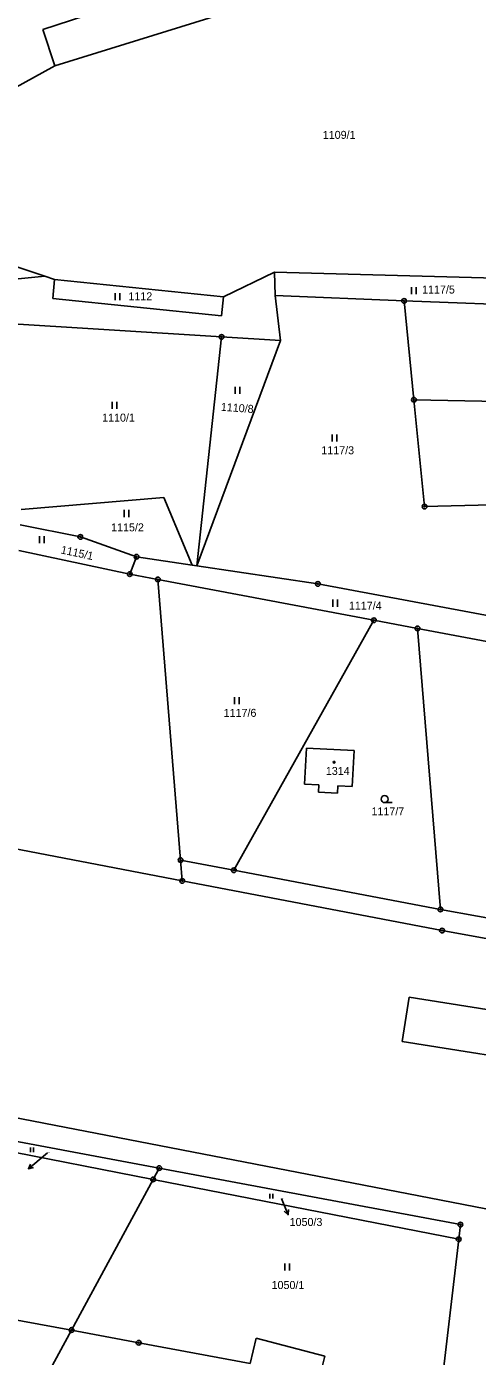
# Model space of a CAD drawing. Extents: x -439246 to -433691, y -1130252 to -1121148.
# Drawn here: x -438252.9 to -438157.2, y -1124120.8 to -1123838.4 of the extents above; entities that cross this region are included whole.
import ezdxf

# ---------------------------------------------------------------- set-up
doc = ezdxf.new("R2010")
doc.units = 0
for name, color, linetype in [('Vrstva 1', 7, 'Continuous'), ('Vrstva 16', 7, 'Continuous'), ('Vrstva 18', 7, 'Continuous'), ('Vrstva 19', 7, 'Continuous'), ('Vrstva 24', 7, 'Continuous'), ('Vrstva 25', 7, 'Continuous'), ('Vrstva 3', 7, 'Continuous'), ('Vrstva 37', 7, 'Continuous'), ('Vrstva 4', 7, 'Continuous')]:
    doc.layers.add(name, color=color, linetype=linetype)

msp = doc.modelspace()

# ---------------------------------------------------------------- linework, layer by layer
at = {"layer": 'Vrstva 1'}
for p, q in [((-438211.48, -1123904.28), (-438259.95, -1123901.23)), ((-438216.73, -1123952.89), (-438211.48, -1123904.28)), ((-438211.48, -1123904.28), (-438199.01, -1123905.06)), ((-438154.2, -1123939.93), (-438168.37, -1123940.3)), ((-438254.26, -1123944.18), (-438241.49, -1123946.76)), ((-438241.49, -1123946.76), (-438229.55, -1123950.97)), ((-438152.43, -1123963.95), (-438191.04, -1123956.73)), ((-438303.51, -1124068.13), (-438226.05, -1124083.23)), ((-438226.05, -1124083.23), (-438243.36, -1124115.21)), ((-438226.05, -1124083.23), (-438161.14, -1124095.94)), ((-438161.14, -1124095.94), (-438165.06, -1124129.7))]:
    msp.add_line(p, q, dxfattribs=at)
for points in [[(-438158.58, -1123809.31), (-438249.45, -1123838.99)], [(-438246.94, -1123846.69), (-438161.58, -1123820.18)], [(-438249.45, -1123838.99), (-438246.94, -1123846.69)], [(-438246.94, -1123846.69), (-438262.62, -1123855.3)], [(-438263.58, -1123886.54), (-438249.05, -1123891.36)], [(-438288.53, -1123895.35), (-438249.05, -1123891.36)], [(-438249.05, -1123891.36), (-438246.95, -1123892.05)], [(-438246.95, -1123892.05), (-438247.36, -1123896.13)], [(-438246.95, -1123892.05), (-438211.07, -1123895.72)], [(-438211.07, -1123895.72), (-438200.28, -1123890.51)], [(-438200.28, -1123890.51), (-438200.11, -1123895.5)], [(-438200.28, -1123890.51), (-438142.74, -1123892.06)], [(-438211.07, -1123895.72), (-438211.49, -1123899.79)], [(-438200.11, -1123895.5), (-438172.73, -1123896.63)], [(-438200.11, -1123895.5), (-438199.01, -1123905.06)], [(-438247.36, -1123896.13), (-438211.49, -1123899.79)], [(-438172.73, -1123896.63), (-438142.74, -1123897.72)], [(-438172.73, -1123896.63), (-438170.63, -1123917.63)], [(-438199.01, -1123905.06), (-438216.73, -1123952.89)], [(-438170.63, -1123917.63), (-438091.35, -1123919.18)], [(-438170.63, -1123917.63), (-438168.37, -1123940.3)], [(-438223.73, -1123938.4), (-438254.07, -1123940.9)], [(-438217.77, -1123952.73), (-438223.73, -1123938.4)], [(-438231, -1123954.66), (-438254.58, -1123949.65)], [(-438229.55, -1123950.97), (-438231, -1123954.66)], [(-438229.55, -1123950.97), (-438217.77, -1123952.73)], [(-438231, -1123954.66), (-438225.03, -1123955.79)], [(-438217.77, -1123952.73), (-438216.73, -1123952.89)], [(-438216.73, -1123952.89), (-438191.04, -1123956.73)], [(-438220.2, -1124015.39), (-438225.03, -1123955.79)], [(-438225.03, -1123955.79), (-438179.13, -1123964.45)], [(-438179.13, -1123964.45), (-438208.88, -1124017.54)], [(-438179.13, -1123964.45), (-438169.88, -1123966.2)], [(-438169.88, -1123966.2), (-438139.3, -1123971.97)], [(-438169.88, -1123966.2), (-438165.03, -1124025.88)], [(-438193.88, -1123999.25), (-438193.49, -1123991.62)], [(-438193.49, -1123991.62), (-438183.35, -1123992.11)], [(-438183.35, -1123992.11), (-438183.74, -1123999.75)], [(-438190.87, -1123999.4), (-438193.88, -1123999.25)], [(-438190.94, -1124000.95), (-438190.87, -1123999.4)], [(-438186.78, -1123999.62), (-438186.86, -1124001.16)], [(-438183.74, -1123999.75), (-438186.78, -1123999.62)], [(-438186.86, -1124001.16), (-438190.94, -1124000.95)], [(-438289.96, -1124006.37), (-438219.84, -1124019.83)], [(-438219.84, -1124019.83), (-438220.2, -1124015.39)], [(-438208.88, -1124017.54), (-438220.2, -1124015.39)], [(-438219.84, -1124019.83), (-438164.68, -1124030.36)], [(-438165.03, -1124025.88), (-438208.88, -1124017.54)], [(-438165.03, -1124025.88), (-438141.4, -1124030.14)], [(-438164.68, -1124030.36), (-438099.78, -1124042.19)], [(-438308.2, -1124065.16), (-438224.74, -1124080.81)], [(-438292.1, -1124062.98), (-438190.79, -1124082.63)], [(-438226.05, -1124083.23), (-438224.74, -1124080.81)], [(-438224.74, -1124080.81), (-438160.78, -1124092.83)], [(-438190.79, -1124082.63), (-438089.34, -1124102.31)], [(-438161.14, -1124095.94), (-438160.78, -1124092.83)], [(-438243.36, -1124115.21), (-438298.17, -1124105.16)], [(-438243.36, -1124115.21), (-438251.93, -1124131.05)], [(-438229.1, -1124117.92), (-438243.36, -1124115.21)], [(-438205.45, -1124122.3), (-438229.1, -1124117.92)], [(-438204.13, -1124116.96), (-438205.45, -1124122.3)], [(-438189.56, -1124120.76), (-438204.13, -1124116.96)], [(-438190.66, -1124124.99), (-438189.56, -1124120.76)]]:
    msp.add_lwpolyline(points, dxfattribs=at)
at = {"layer": 'Vrstva 16'}
for p, q in [((-438250.22, -1124079.06), (-438252.53, -1124080.97)), ((-438198.51, -1124087.96), (-438197.34, -1124090.72))]:
    msp.add_line(p, q, dxfattribs=at)
for points in [[(-438248.44, -1124077.58), (-438250.22, -1124079.06)], [(-438251.44, -1124080.72), (-438252.53, -1124080.97), (-438252.08, -1124079.95)], [(-438198.8, -1124087.25), (-438198.51, -1124087.96)], [(-438197.27, -1124089.6), (-438197.34, -1124090.72), (-438198.19, -1124090)]]:
    msp.add_lwpolyline(points, dxfattribs=at)
at = {"layer": 'Vrstva 24'}
for centre, radius in [((-438172.73, -1123896.63), 0.5), ((-438172.73, -1123896.63), 0.1), ((-438211.48, -1123904.28), 0.5), ((-438211.48, -1123904.28), 0.1), ((-438170.63, -1123917.63), 0.5), ((-438170.63, -1123917.63), 0.1), ((-438168.37, -1123940.3), 0.5), ((-438168.37, -1123940.3), 0.1), ((-438241.49, -1123946.76), 0.5), ((-438241.49, -1123946.76), 0.1), ((-438229.55, -1123950.97), 0.5), ((-438229.55, -1123950.97), 0.1), ((-438231, -1123954.66), 0.5), ((-438231, -1123954.66), 0.1), ((-438225.03, -1123955.79), 0.5), ((-438225.03, -1123955.79), 0.1), ((-438191.04, -1123956.73), 0.5), ((-438191.04, -1123956.73), 0.1), ((-438179.13, -1123964.45), 0.5), ((-438179.13, -1123964.45), 0.1), ((-438169.88, -1123966.2), 0.5), ((-438169.88, -1123966.2), 0.1), ((-438220.2, -1124015.39), 0.5), ((-438220.2, -1124015.39), 0.1), ((-438208.88, -1124017.54), 0.5), ((-438208.88, -1124017.54), 0.1), ((-438219.84, -1124019.83), 0.5), ((-438219.84, -1124019.83), 0.1), ((-438165.03, -1124025.88), 0.5), ((-438165.03, -1124025.88), 0.1), ((-438164.68, -1124030.36), 0.5), ((-438164.68, -1124030.36), 0.1), ((-438224.74, -1124080.81), 0.5), ((-438224.74, -1124080.81), 0.1), ((-438226.05, -1124083.23), 0.5), ((-438226.05, -1124083.23), 0.1), ((-438160.78, -1124092.83), 0.5), ((-438160.78, -1124092.83), 0.1), ((-438161.14, -1124095.94), 0.5), ((-438161.14, -1124095.94), 0.1), ((-438243.36, -1124115.21), 0.5), ((-438243.36, -1124115.21), 0.1), ((-438229.1, -1124117.92), 0.5), ((-438229.1, -1124117.92), 0.1)]:
    msp.add_circle(centre, radius, dxfattribs=at)
at = {"layer": 'Vrstva 25'}
for p, q in [((-438234.1, -1123896.49), (-438234.1, -1123894.99)), ((-438233.1, -1123896.49), (-438233.1, -1123894.99)), ((-438171.18, -1123895.22), (-438171.18, -1123893.72)), ((-438170.18, -1123895.22), (-438170.18, -1123893.72)), ((-438208.64, -1123916.38), (-438208.64, -1123914.88)), ((-438207.64, -1123916.38), (-438207.64, -1123914.88)), ((-438234.75, -1123919.56), (-438234.75, -1123918.06)), ((-438233.75, -1123919.56), (-438233.75, -1123918.06)), ((-438188.04, -1123926.5), (-438188.04, -1123925)), ((-438187.04, -1123926.5), (-438187.04, -1123925)), ((-438232.2, -1123942.53), (-438232.2, -1123941.03)), ((-438231.2, -1123942.53), (-438231.2, -1123941.03)), ((-438250.19, -1123948.09), (-438250.19, -1123946.59)), ((-438249.19, -1123948.09), (-438249.19, -1123946.59)), ((-438187.86, -1123961.57), (-438187.86, -1123960.07)), ((-438186.86, -1123961.57), (-438186.86, -1123960.07)), ((-438208.73, -1123982.27), (-438208.73, -1123980.77)), ((-438207.73, -1123982.27), (-438207.73, -1123980.77)), ((-438176.87, -1124003.19), (-438175.27, -1124003.19)), ((-438252.08, -1124077.45), (-438252.08, -1124076.45)), ((-438251.41, -1124077.45), (-438251.41, -1124076.45)), ((-438201.24, -1124087.26), (-438201.24, -1124086.26)), ((-438200.58, -1124087.26), (-438200.58, -1124086.26)), ((-438198.04, -1124102.6), (-438198.04, -1124101.1)), ((-438197.04, -1124102.6), (-438197.04, -1124101.1))]:
    msp.add_line(p, q, dxfattribs=at)
for centre, radius in [((-438187.59, -1123994.61), 0.175), ((-438176.87, -1124002.44), 0.75)]:
    msp.add_circle(centre, radius, dxfattribs=at)
at = {"layer": 'Vrstva 3'}
for points in [[(-438193.88, -1123999.25), (-438193.49, -1123991.62)], [(-438193.49, -1123991.62), (-438183.35, -1123992.11)], [(-438183.35, -1123992.11), (-438183.74, -1123999.75)], [(-438190.87, -1123999.4), (-438193.88, -1123999.25)], [(-438190.94, -1124000.95), (-438190.87, -1123999.4)], [(-438186.78, -1123999.62), (-438186.86, -1124001.16)], [(-438183.74, -1123999.75), (-438186.78, -1123999.62)], [(-438186.86, -1124001.16), (-438190.94, -1124000.95)], [(-438171.68, -1124044.51), (-438173.17, -1124053.9)], [(-438128.37, -1124051.39), (-438171.68, -1124044.51)], [(-438173.17, -1124053.9), (-438139.25, -1124059.29)], [(-438204.13, -1124116.96), (-438205.45, -1124122.3)], [(-438189.56, -1124120.76), (-438204.13, -1124116.96)], [(-438190.66, -1124124.99), (-438189.56, -1124120.76)]]:
    msp.add_lwpolyline(points, dxfattribs=at)
at = {"layer": 'Vrstva 37'}
msp.add_circle((-438187.59, -1123994.61), 0.175, dxfattribs=at)
at = {"layer": 'Vrstva 4'}
for points in [[(-438171.68, -1124044.51), (-438173.17, -1124053.9)], [(-438128.37, -1124051.39), (-438171.68, -1124044.51)], [(-438173.17, -1124053.9), (-438139.25, -1124059.29)]]:
    msp.add_lwpolyline(points, dxfattribs=at)

# ---------------------------------------------------------------- texts
at = {"layer": 'Vrstva 16'}
msp.add_text('1050/3', height=1.7, dxfattribs=at).set_placement((-438197.04, -1124093.11))
at = {"layer": 'Vrstva 18'}
for s, height, p in [('1109/1', 1.7, (-438190, -1123862.2)), ('1112', 1.7, (-438231.28, -1123896.49)), ('1117/5', 1.7, (-438168.91, -1123895.05)), ('1110/1', 1.7, (-438236.86, -1123922.26)), ('1117/3', 1.7, (-438190.31, -1123929.2)), ('1115/2', 1.7, (-438234.95, -1123945.57)), ('1117/4', 1.7, (-438184.46, -1123962.2)), ('1117/6', 1.7, (-438211.05, -1123984.97)), ('1117/7', 1.7, (-438179.66, -1124005.89)), ('1050/4', 0.1, (-438248.44, -1124077.58)), ('1050/3', 0.1, (-438198.8, -1124087.25)), ('1050/1', 1.7, (-438200.87, -1124106.5))]:
    msp.add_text(s, height=height, dxfattribs=at).set_placement(p)
for s, rotation, p in [('1110/8', 355.8032, (-438211.69, -1123919.94)), ('1115/1', 348.0048, (-438245.74, -1123950.24))]:
    msp.add_text(s, height=1.7, rotation=rotation, dxfattribs=at).set_placement(p)
at = {"layer": 'Vrstva 19'}
msp.add_text('1314', height=1.7, dxfattribs=at).set_placement((-438189.35, -1123997.31))

doc.saveas('drawing.dxf')
